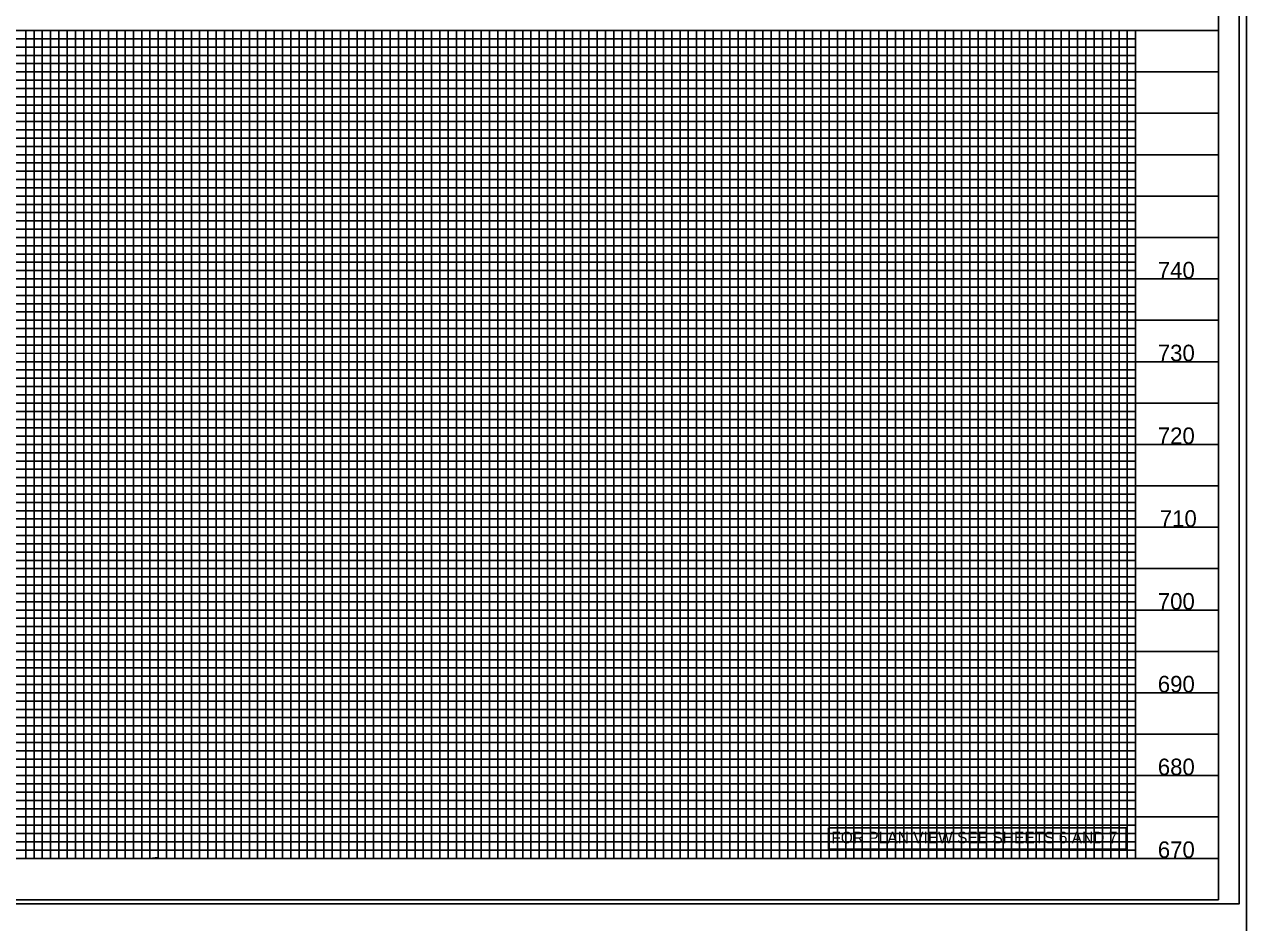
# Model space of a CAD drawing. Extents: x 1754992 to 1757273, y 732111 to 735411.
# Drawn here: x 1756127 to 1756865, y 733222 to 733764 of the extents above; entities that cross this region are included whole.
import ezdxf

# ---------------------------------------------------------------- set-up
doc = ezdxf.new("R2010")
doc.units = 0
for name, color, linetype in [('ENG SEALS CELL', 7, 'Continuous'), ('Prop DSN Text', 7, 'Continuous'), ('Scratch_Level_3', 7, 'Continuous'), ('Sheet DOT Grid CELL', 7, 'Continuous'), ('Sheet PE Seal Cell', 7, 'Continuous'), ('Sheet Plot Border Inside CELL', 7, 'Continuous'), ('Sheet Plot Border Outside CELL', 7, 'Continuous'), ('Sheet Profile CELL', 7, 'Continuous'), ('Sheet Profile Grid Major CELL', 7, 'Continuous'), ('Sheet Profile Grid Middle CELL', 7, 'Continuous'), ('Sheet Profile Grid Minor CELL', 7, 'Continuous')]:
    doc.layers.add(name, color=color, linetype=linetype)

msp = doc.modelspace()

# ---------------------------------------------------------------- linework, layer by layer
at = {"layer": 'ENG SEALS CELL'}
msp.add_lwpolyline([(1756612.34, 733279.29), (1756792.01, 733279.29), (1756792.01, 733266.28), (1756612.34, 733266.28)], close=True, dxfattribs=at)
at = {"layer": 'Scratch_Level_3'}
msp.add_lwpolyline([(1755397.67, 733760.78), (1756797.67, 733760.78), (1756797.67, 733260.78), (1755397.67, 733260.78)], close=True, dxfattribs=at)
at = {"layer": 'Sheet DOT Grid CELL'}
for p, q in [((1755347.67, 733760.78), (1756847.56, 733760.78)), ((1756147.67, 733760.78), (1756147.67, 733260.78)), ((1756197.67, 733760.78), (1756197.67, 733260.78)), ((1756247.67, 733760.78), (1756247.67, 733260.78)), ((1756297.67, 733760.78), (1756297.67, 733260.78)), ((1756347.67, 733760.78), (1756347.67, 733260.78)), ((1756397.67, 733760.78), (1756397.67, 733260.78)), ((1756447.67, 733760.78), (1756447.67, 733260.78)), ((1756497.67, 733760.78), (1756497.67, 733260.78)), ((1756547.67, 733760.78), (1756547.67, 733260.78)), ((1756597.67, 733760.78), (1756597.67, 733260.78)), ((1756647.67, 733760.78), (1756647.67, 733260.78)), ((1756697.67, 733760.78), (1756697.67, 733260.78)), ((1756747.67, 733760.78), (1756747.67, 733260.78)), ((1756797.67, 733760.78), (1756797.67, 733260.78)), ((1755347.67, 733710.78), (1756847.56, 733710.78)), ((1755347.67, 733660.78), (1756847.56, 733660.78)), ((1755347.67, 733610.78), (1756847.56, 733610.78)), ((1755347.67, 733560.78), (1756847.56, 733560.78)), ((1755347.67, 733510.78), (1756847.56, 733510.78)), ((1755347.67, 733460.78), (1756847.56, 733460.78)), ((1755347.67, 733410.78), (1756847.56, 733410.78)), ((1755347.67, 733360.78), (1756847.56, 733360.78)), ((1755347.67, 733310.78), (1756847.56, 733310.78))]:
    msp.add_line(p, q, dxfattribs=at)
at = {"layer": 'Sheet Plot Border Inside CELL'}
msp.add_lwpolyline([(1755193.67, 733233.23), (1756860.17, 733233.23), (1756860.17, 734288.33), (1755193.67, 734288.33)], close=True, dxfattribs=at)
at = {"layer": 'Sheet Plot Border Outside CELL'}
msp.add_lwpolyline([(1755180.67, 733210.78), (1756864.67, 733210.78), (1756864.67, 734310.78), (1755180.67, 734310.78)], close=True, dxfattribs=at)
at = {"layer": 'Sheet Profile CELL'}
for p, q in [((1755347.67, 733760.78), (1756847.67, 733760.78)), ((1756847.67, 733260.78), (1755347.67, 733260.78)), ((1755347.67, 733235.78), (1756847.67, 733235.78))]:
    msp.add_line(p, q, dxfattribs=at)
msp.add_lwpolyline([(1756847.67, 734285.78), (1755347.67, 734285.78), (1755347.67, 733235.78), (1756847.67, 733235.78)], close=True, dxfattribs=at)
at = {"layer": 'Sheet Profile Grid Major CELL'}
for p, q in [((1756147.67, 733760.78), (1756197.67, 733760.78)), ((1756247.67, 733760.78), (1756297.67, 733760.78)), ((1756347.67, 733760.78), (1756397.67, 733760.78)), ((1756447.67, 733760.78), (1756497.67, 733760.78)), ((1756547.67, 733760.78), (1756597.67, 733760.78)), ((1756647.67, 733760.78), (1756697.67, 733760.78)), ((1756747.67, 733760.78), (1756797.67, 733760.78)), ((1756747.67, 733260.78), (1756747.67, 733260.78))]:
    msp.add_line(p, q, dxfattribs=at)
for points in [[(1756097.67, 733260.78), (1756147.67, 733260.78), (1756147.67, 733760.78), (1756197.67, 733760.78), (1756197.67, 733260.78), (1756247.67, 733260.78), (1756247.67, 733760.78), (1756297.67, 733760.78), (1756297.67, 733260.78), (1756347.67, 733260.78), (1756347.67, 733760.78), (1756397.67, 733760.78), (1756397.67, 733260.78), (1756447.67, 733260.78), (1756447.67, 733760.78), (1756497.67, 733760.78), (1756497.67, 733260.78), (1756547.67, 733260.78), (1756547.67, 733760.78), (1756597.67, 733760.78), (1756597.67, 733260.78), (1756647.67, 733260.78), (1756647.67, 733760.78), (1756697.67, 733760.78), (1756697.67, 733260.78), (1756747.67, 733260.78), (1756747.67, 733260.78), (1756747.67, 733760.78), (1756797.67, 733760.78), (1756797.67, 733260.78)], [(1756847.67, 733710.78), (1755347.67, 733710.78)], [(1756847.67, 733660.78), (1755347.67, 733660.78), (1755347.67, 733610.78), (1756847.67, 733610.78)], [(1756847.67, 733560.78), (1755347.67, 733560.78), (1755347.67, 733510.78), (1756847.67, 733510.78)], [(1756847.67, 733460.78), (1755347.67, 733460.78), (1755347.67, 733410.78), (1756847.67, 733410.78)], [(1756847.67, 733360.78), (1755347.67, 733360.78), (1755347.67, 733360.78), (1755347.67, 733310.78), (1756847.67, 733310.78)], [(1756847.67, 733260.78), (1755347.67, 733260.78)]]:
    msp.add_lwpolyline(points, dxfattribs=at)
at = {"layer": 'Sheet Profile Grid Middle CELL'}
for points in [[(1756122.67, 733260.78), (1756172.67, 733260.78), (1756172.67, 733760.78), (1756222.67, 733760.78), (1756222.67, 733260.78), (1756272.67, 733260.78), (1756272.67, 733760.78), (1756322.67, 733760.78), (1756322.67, 733260.78), (1756372.67, 733260.78), (1756372.67, 733760.78), (1756422.67, 733760.78), (1756422.67, 733260.78), (1756472.67, 733260.78), (1756472.67, 733760.78), (1756522.67, 733760.78), (1756522.67, 733260.78), (1756572.67, 733260.78), (1756572.67, 733760.78), (1756622.67, 733760.78), (1756622.67, 733260.78), (1756672.67, 733260.78), (1756672.67, 733760.78), (1756722.67, 733760.78), (1756722.67, 733260.78), (1756772.67, 733260.78), (1756772.67, 733760.78)], [(1755347.67, 733735.78), (1756847.67, 733735.78)], [(1756847.67, 733685.78), (1755347.67, 733685.78), (1755347.67, 733635.78), (1756847.67, 733635.78)], [(1756847.67, 733585.78), (1755347.67, 733585.78), (1755347.67, 733535.78), (1756847.67, 733535.78)], [(1756847.67, 733485.78), (1755347.67, 733485.78), (1755347.67, 733435.78), (1756847.67, 733435.78)], [(1756847.67, 733385.78), (1755347.67, 733385.78), (1755347.67, 733335.78), (1756847.67, 733335.78)], [(1756847.67, 733285.78), (1755347.67, 733285.78)]]:
    msp.add_lwpolyline(points, dxfattribs=at)
at = {"layer": 'Sheet Profile Grid Minor CELL'}
for p, q in [((1755397.67, 733755.78), (1756797.67, 733755.78)), ((1756797.67, 733750.78), (1755397.67, 733750.78)), ((1755397.67, 733745.78), (1756797.67, 733745.78)), ((1756797.67, 733740.78), (1755397.67, 733740.78)), ((1755397.67, 733730.78), (1756797.67, 733730.78)), ((1756797.67, 733725.78), (1755397.67, 733725.78)), ((1755397.67, 733720.78), (1756797.67, 733720.78)), ((1756797.67, 733715.78), (1755397.67, 733715.78)), ((1755397.67, 733705.78), (1756797.67, 733705.78)), ((1756797.67, 733700.78), (1755397.67, 733700.78)), ((1755397.67, 733695.78), (1756797.67, 733695.78)), ((1756797.67, 733690.78), (1755397.67, 733690.78)), ((1755397.67, 733680.78), (1756797.67, 733680.78)), ((1756797.67, 733675.78), (1755397.67, 733675.78)), ((1755397.67, 733670.78), (1756797.67, 733670.78)), ((1756797.67, 733665.78), (1755397.67, 733665.78)), ((1755397.67, 733655.78), (1756797.67, 733655.78)), ((1756797.67, 733650.78), (1755397.67, 733650.78)), ((1755397.67, 733645.78), (1756797.67, 733645.78)), ((1756797.67, 733640.78), (1755397.67, 733640.78)), ((1755397.67, 733630.78), (1756797.67, 733630.78)), ((1756797.67, 733625.78), (1755397.67, 733625.78)), ((1755397.67, 733620.78), (1756797.67, 733620.78)), ((1756797.67, 733615.78), (1755397.67, 733615.78)), ((1755397.67, 733605.78), (1756797.67, 733605.78)), ((1756797.67, 733600.78), (1755397.67, 733600.78)), ((1755397.67, 733595.78), (1756797.67, 733595.78)), ((1756797.67, 733590.78), (1755397.67, 733590.78)), ((1755397.67, 733580.78), (1756797.67, 733580.78)), ((1756797.67, 733575.78), (1755397.67, 733575.78)), ((1755397.67, 733570.78), (1756797.67, 733570.78)), ((1756797.67, 733565.78), (1755397.67, 733565.93)), ((1755397.67, 733555.78), (1756797.67, 733555.78)), ((1756797.67, 733550.78), (1755397.67, 733550.78)), ((1755397.67, 733545.78), (1756797.67, 733545.78)), ((1756797.67, 733540.78), (1755397.67, 733540.78)), ((1755397.67, 733530.78), (1756797.67, 733530.78)), ((1756797.67, 733525.78), (1755397.67, 733525.78)), ((1755397.67, 733520.78), (1756797.67, 733520.78)), ((1756797.67, 733515.78), (1755397.67, 733515.78)), ((1755397.67, 733505.78), (1756797.67, 733505.78)), ((1756797.67, 733500.78), (1755397.67, 733500.78)), ((1755397.67, 733495.78), (1756797.67, 733495.78)), ((1756797.67, 733490.78), (1755397.67, 733490.78)), ((1755397.67, 733480.78), (1756797.67, 733480.78)), ((1756797.67, 733475.78), (1755397.67, 733475.78)), ((1755397.67, 733470.78), (1756797.67, 733470.78)), ((1756797.67, 733465.78), (1755397.67, 733465.78)), ((1755397.67, 733455.78), (1756797.67, 733455.78)), ((1756797.67, 733450.78), (1755397.67, 733450.78)), ((1755397.67, 733445.78), (1756797.67, 733445.78)), ((1756797.67, 733440.78), (1755397.67, 733440.78)), ((1755397.67, 733430.78), (1756797.67, 733430.78)), ((1756797.67, 733425.78), (1755397.67, 733425.78)), ((1755397.67, 733420.78), (1756797.67, 733420.78)), ((1756797.67, 733415.78), (1755397.67, 733415.78)), ((1755397.67, 733405.78), (1756797.67, 733405.78)), ((1756797.67, 733400.78), (1755397.67, 733400.78)), ((1755397.67, 733395.78), (1756797.67, 733395.78)), ((1756797.67, 733390.78), (1755397.67, 733390.78)), ((1755397.67, 733380.78), (1756797.67, 733380.78)), ((1756797.67, 733375.78), (1755397.67, 733375.78)), ((1755397.67, 733370.78), (1756797.67, 733370.78)), ((1756797.67, 733365.78), (1755397.67, 733365.78)), ((1755397.67, 733355.78), (1756797.67, 733355.78)), ((1756797.67, 733350.78), (1755397.67, 733350.78)), ((1755397.67, 733345.78), (1756797.67, 733345.78)), ((1756797.67, 733340.78), (1755397.67, 733340.78)), ((1755397.67, 733330.78), (1756797.67, 733330.78)), ((1756797.67, 733325.78), (1755397.67, 733325.78)), ((1755397.67, 733320.78), (1756797.67, 733320.78)), ((1756797.67, 733315.78), (1755397.67, 733315.78)), ((1755397.67, 733305.78), (1756797.67, 733305.78)), ((1756797.67, 733300.78), (1755397.67, 733300.78)), ((1755397.67, 733295.78), (1756797.67, 733295.78)), ((1756797.67, 733290.78), (1755397.67, 733290.78)), ((1755397.67, 733280.78), (1756797.67, 733280.78)), ((1756797.67, 733275.78), (1755397.67, 733275.78)), ((1755397.67, 733270.78), (1756797.67, 733270.78)), ((1755397.67, 733265.78), (1756797.67, 733265.78)), ((1756797.67, 733265.78), (1756797.67, 733265.78))]:
    msp.add_line(p, q, dxfattribs=at)
for points in [[(1756117.67, 733760.78), (1756127.67, 733760.78), (1756127.67, 733260.78), (1756132.67, 733260.78), (1756132.67, 733760.78), (1756137.67, 733760.78), (1756137.67, 733260.78), (1756142.67, 733260.78), (1756142.67, 733760.78), (1756152.67, 733760.78), (1756152.67, 733260.78), (1756157.67, 733260.78), (1756157.67, 733760.78), (1756162.67, 733760.78), (1756162.67, 733260.78), (1756167.67, 733260.78), (1756167.67, 733760.78), (1756177.67, 733760.78), (1756177.67, 733260.78), (1756182.67, 733260.78), (1756182.67, 733760.78), (1756187.67, 733760.78), (1756187.67, 733260.78), (1756192.67, 733260.78), (1756192.67, 733760.78), (1756202.67, 733760.78), (1756202.67, 733260.78), (1756207.37, 733261.33), (1756207.67, 733260.78), (1756207.67, 733760.78), (1756212.67, 733760.78), (1756212.67, 733260.78), (1756217.67, 733260.78), (1756217.67, 733760.78), (1756227.67, 733760.78), (1756227.67, 733260.78), (1756232.67, 733260.78)], [(1756232.67, 733260.78), (1756232.67, 733760.78), (1756237.67, 733760.78), (1756237.67, 733260.78), (1756242.67, 733260.78), (1756242.67, 733760.78), (1756252.67, 733760.78), (1756252.67, 733260.78), (1756257.67, 733260.78), (1756257.67, 733760.78), (1756262.67, 733760.78), (1756262.67, 733260.78), (1756267.67, 733260.78), (1756267.67, 733760.78), (1756277.67, 733760.78), (1756277.67, 733260.78), (1756282.67, 733260.78), (1756282.67, 733760.78), (1756287.67, 733760.78), (1756287.67, 733260.78), (1756292.67, 733260.78), (1756292.67, 733760.78), (1756302.67, 733760.78), (1756302.67, 733260.78), (1756307.67, 733260.78), (1756307.67, 733760.78), (1756312.67, 733760.78), (1756312.67, 733260.78), (1756317.67, 733260.78), (1756317.67, 733760.78), (1756327.67, 733760.78), (1756327.67, 733260.78), (1756332.67, 733260.78), (1756332.67, 733760.78), (1756337.67, 733760.78), (1756337.67, 733260.78), (1756342.67, 733260.78), (1756342.67, 733760.78), (1756352.67, 733760.78), (1756352.67, 733260.78), (1756357.67, 733260.78), (1756357.67, 733760.78), (1756362.67, 733760.78), (1756362.67, 733260.78), (1756367.67, 733260.78), (1756367.67, 733760.78), (1756377.67, 733760.78), (1756377.67, 733260.78), (1756382.67, 733260.78), (1756382.67, 733760.78), (1756387.67, 733760.78), (1756387.67, 733260.78), (1756392.67, 733260.78), (1756392.67, 733760.78), (1756402.67, 733760.78), (1756402.67, 733260.78), (1756407.67, 733260.78), (1756407.67, 733760.78), (1756412.67, 733760.78), (1756412.67, 733260.78), (1756417.67, 733260.78), (1756417.67, 733760.78), (1756427.67, 733760.78), (1756427.67, 733260.78), (1756432.67, 733260.78), (1756432.67, 733760.78), (1756437.67, 733760.78), (1756437.67, 733260.78), (1756442.67, 733260.78), (1756442.67, 733760.78), (1756452.67, 733760.78), (1756452.67, 733260.78), (1756457.67, 733260.78), (1756457.67, 733760.78), (1756462.67, 733760.78), (1756462.67, 733260.78), (1756467.67, 733260.78), (1756467.67, 733760.78), (1756477.67, 733760.78), (1756477.67, 733260.78), (1756482.67, 733260.78), (1756482.67, 733760.78), (1756487.67, 733760.78), (1756487.67, 733260.78), (1756492.67, 733260.78), (1756492.67, 733760.78), (1756502.67, 733760.78), (1756502.67, 733260.78), (1756507.67, 733260.78), (1756507.67, 733760.78), (1756512.67, 733760.78), (1756512.67, 733260.78), (1756517.67, 733260.78), (1756517.67, 733760.78), (1756527.67, 733760.78), (1756527.67, 733260.78), (1756532.67, 733260.78), (1756532.67, 733760.78), (1756537.67, 733760.78), (1756537.67, 733260.78)], [(1756537.67, 733260.78), (1756542.67, 733260.78), (1756542.67, 733760.78), (1756552.67, 733760.78), (1756552.67, 733260.78), (1756557.67, 733260.78), (1756557.67, 733760.78), (1756562.67, 733760.78), (1756562.67, 733260.78), (1756567.67, 733260.78), (1756567.67, 733760.78), (1756577.67, 733760.78), (1756577.67, 733260.78), (1756582.67, 733260.78), (1756582.67, 733760.78), (1756587.67, 733760.78), (1756587.67, 733260.78), (1756592.67, 733260.78), (1756592.67, 733760.78), (1756602.67, 733760.78), (1756602.67, 733260.78), (1756607.67, 733260.78), (1756607.67, 733760.78), (1756612.67, 733760.78), (1756612.67, 733260.78), (1756617.67, 733260.78), (1756617.67, 733760.78), (1756627.67, 733760.78), (1756627.67, 733260.78), (1756632.67, 733260.78), (1756632.67, 733760.78), (1756637.67, 733760.78), (1756637.67, 733260.78), (1756642.67, 733260.78), (1756642.67, 733760.78), (1756652.67, 733760.78), (1756652.67, 733260.78), (1756657.67, 733260.78), (1756657.67, 733760.78), (1756662.67, 733760.78), (1756662.67, 733260.78), (1756667.67, 733260.78), (1756667.67, 733760.78), (1756677.67, 733760.78), (1756677.67, 733260.78), (1756682.67, 733260.78), (1756682.67, 733760.78), (1756687.67, 733760.78), (1756687.67, 733260.78), (1756692.67, 733260.78), (1756692.67, 733760.78), (1756702.67, 733760.78), (1756702.67, 733260.78), (1756707.67, 733260.78), (1756707.67, 733760.78), (1756712.67, 733760.78), (1756712.67, 733260.78), (1756717.67, 733260.78), (1756717.67, 733760.78), (1756727.67, 733760.78), (1756727.67, 733260.78), (1756732.67, 733260.78), (1756732.67, 733760.78), (1756737.67, 733760.78), (1756737.67, 733260.78), (1756742.67, 733260.78), (1756742.67, 733760.78), (1756752.67, 733760.78), (1756752.67, 733260.78), (1756757.67, 733260.78), (1756757.67, 733760.78), (1756762.67, 733760.78), (1756762.67, 733260.78), (1756767.67, 733260.78), (1756767.67, 733760.78), (1756777.67, 733760.78), (1756777.67, 733260.78), (1756782.67, 733260.78), (1756782.67, 733760.78), (1756787.67, 733760.78), (1756787.67, 733260.78), (1756792.67, 733260.78), (1756792.67, 733760.78), (1756797.67, 733760.78)]]:
    msp.add_lwpolyline(points, dxfattribs=at)

# ---------------------------------------------------------------- texts
at = {"layer": 'Prop DSN Text'}
for s, p in [('740', (1756811.1, 733611.03)), ('730', (1756811.1, 733561.03)), ('720', (1756811.1, 733511.03)), ('710', (1756812.3, 733461.03)), ('700', (1756811.1, 733411.03)), ('690', (1756811.1, 733361.03)), ('680', (1756811.1, 733311.03)), ('670', (1756811.1, 733261.03))]:
    msp.add_text(s, height=10, dxfattribs=at).set_placement(p)
at = {"layer": 'Sheet PE Seal Cell'}
msp.add_text('FOR PLAN VIEW SEE SHEETS 6 AND 7', height=7, dxfattribs=at).set_placement((1756613.98, 733269.86))

doc.saveas('drawing.dxf')
